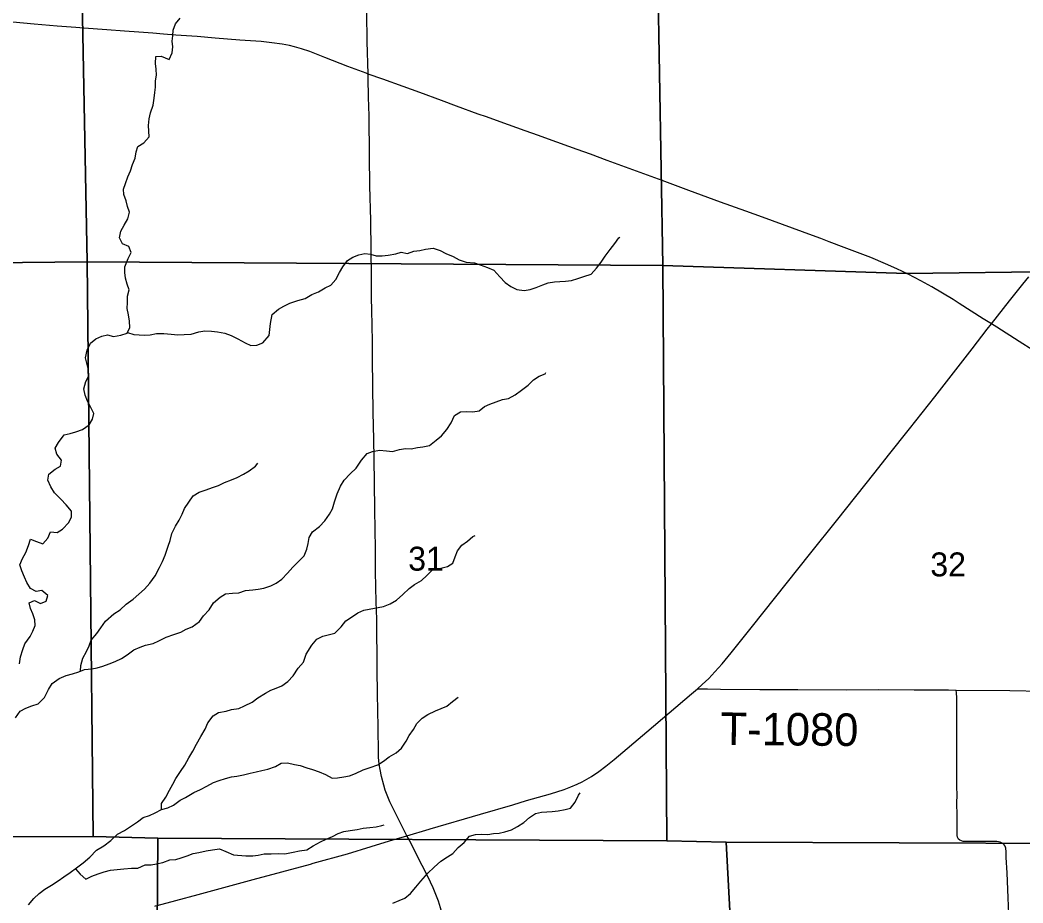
# Model space of a CAD drawing. Extents: x 0 to 34, y 0 to 22.
# Drawn here: x 11.363 to 13.115, y 13.199 to 14.742 of the extents above; entities that cross this region are included whole.
import ezdxf

# ---------------------------------------------------------------- set-up
doc = ezdxf.new("R2010")
doc.units = 0
for name, color, linetype in [('GM_X_Minor_River', 7, 'Continuous'), ('GM_X_Section', 7, 'Continuous'), ('GM_X_Section_Text', 7, 'Continuous'), ('GM_X_State_Route', 7, 'Continuous'), ('GM_X_Township_Road', 7, 'Continuous'), ('GM_X_Township_Road_Text', 7, 'Continuous'), ('GM_X_US_Route', 7, 'Continuous')]:
    doc.layers.add(name, color=color, linetype=linetype)

msp = doc.modelspace()

# ---------------------------------------------------------------- linework, layer by layer
at = {"layer": 'GM_X_Minor_River'}
for points in [[(11.4605, 14.0224), (11.4723, 14.0268), (11.4841, 14.0347), (11.4899, 14.0445), (11.4922, 14.0543), (11.4867, 14.065), (11.4811, 14.076), (11.477, 14.0867), (11.4748, 14.0977), (11.478, 14.1102), (11.4833, 14.1204), (11.483, 14.1307), (11.4805, 14.1402), (11.4779, 14.1516), (11.4803, 14.1652), (11.4861, 14.1773), (11.4956, 14.1848), (11.5063, 14.1896), (11.5161, 14.1918), (11.5267, 14.1891), (11.5392, 14.1912), (11.5502, 14.1949), (11.5552, 14.2051), (11.5546, 14.2161), (11.5528, 14.2267), (11.5506, 14.2378), (11.5511, 14.2488), (11.5508, 14.2594), (11.5539, 14.2704), (11.5502, 14.2806), (11.5473, 14.2909), (11.5462, 14.3008), (11.5463, 14.3107), (11.5521, 14.3254), (11.5575, 14.336), (11.5534, 14.3463), (11.5421, 14.3509), (11.5373, 14.3616), (11.5396, 14.373), (11.545, 14.3839), (11.5516, 14.3945), (11.5547, 14.4066), (11.551, 14.4161), (11.5484, 14.426), (11.5447, 14.437), (11.544, 14.4465), (11.5475, 14.4567), (11.5518, 14.4681), (11.5561, 14.4787), (11.5596, 14.4896), (11.5646, 14.501), (11.5662, 14.5116), (11.5689, 14.5214), (11.5796, 14.5274), (11.5887, 14.5379), (11.5881, 14.5482), (11.5878, 14.5576), (11.5886, 14.5694), (11.5914, 14.58), (11.596, 14.5932), (11.5976, 14.6057), (11.5985, 14.6156), (11.5997, 14.6251), (11.5998, 14.6357), (11.6014, 14.6459), (11.6011, 14.6562), (11.5997, 14.6664), (11.6002, 14.6782), (11.61, 14.6788), (11.6236, 14.6734), (11.629, 14.6847), (11.6302, 14.6953), (11.6292, 14.7052), (11.6304, 14.7147), (11.6308, 14.7242), (11.6351, 14.7355), (11.6431, 14.7453)], [(11.5509, 14.1962), (11.5623, 14.1925), (11.5805, 14.1912), (11.5907, 14.1922), (11.6017, 14.1944), (11.6142, 14.1943), (11.6275, 14.193), (11.6392, 14.1921), (11.6498, 14.1928), (11.6623, 14.1934), (11.6756, 14.1971), (11.6858, 14.1989), (11.6979, 14.1984), (11.7082, 14.1975), (11.721, 14.1947), (11.7323, 14.1908), (11.744, 14.185), (11.7565, 14.1781), (11.7666, 14.1731), (11.7769, 14.1737), (11.7875, 14.1778), (11.7982, 14.191), (11.7998, 14.2016), (11.8007, 14.2118), (11.8035, 14.2277), (11.8145, 14.2367), (11.824, 14.2423), (11.8347, 14.2471), (11.8487, 14.2523), (11.8613, 14.2556), (11.8731, 14.2627), (11.8848, 14.2671), (11.8963, 14.2742), (11.9061, 14.2791), (11.9149, 14.2889), (11.9215, 14.3009), (11.9269, 14.3107), (11.9353, 14.3217), (11.9448, 14.3276), (11.9551, 14.3321), (11.9657, 14.3339), (11.9755, 14.333), (11.9853, 14.3299), (11.9956, 14.3298), (12.0062, 14.3312), (12.0198, 14.3337), (12.0293, 14.3367), (12.0403, 14.3343), (12.0509, 14.338), (12.0615, 14.3394), (12.0718, 14.342), (12.0847, 14.3434), (12.0971, 14.3394), (12.1073, 14.3344), (12.1198, 14.329), (12.1303, 14.3232), (12.1428, 14.3189), (12.1571, 14.318), (12.167, 14.3145), (12.1798, 14.3098), (12.1911, 14.3048), (12.2016, 14.2933), (12.2106, 14.2837), (12.2208, 14.2764), (12.2313, 14.2713), (12.2438, 14.2697), (12.2544, 14.2711), (12.2651, 14.2748), (12.2765, 14.2796), (12.286, 14.2826), (12.2966, 14.2844), (12.3061, 14.2854), (12.3163, 14.2857), (12.3265, 14.2871), (12.3375, 14.2904), (12.3482, 14.2937), (12.3607, 14.2982), (12.3703, 14.3083), (12.3783, 14.3192), (12.3852, 14.3294), (12.394, 14.3411), (12.4021, 14.3516), (12.4093, 14.3618), (12.4109, 14.3629)], [(11.3552, 13.5229), (11.3636, 13.5346), (11.3735, 13.5398), (11.3838, 13.5435), (11.3952, 13.5472), (11.4059, 13.5581), (11.4132, 13.5724), (11.4193, 13.5826), (11.4319, 13.5916), (11.4437, 13.5968), (11.4547, 13.5997), (11.4661, 13.6034), (11.476, 13.6071), (11.4885, 13.6085), (11.4979, 13.6103), (11.5078, 13.6132), (11.5192, 13.6173), (11.5295, 13.6214), (11.5405, 13.6266), (11.5504, 13.6326), (11.5622, 13.6415), (11.5732, 13.646), (11.5827, 13.6497), (11.5956, 13.6526), (11.6059, 13.6571), (11.6188, 13.6634), (11.6317, 13.6682), (11.6439, 13.6726), (11.6534, 13.6775), (11.664, 13.6815), (11.6766, 13.6909), (11.6835, 13.7007), (11.6934, 13.7116), (11.7015, 13.7237), (11.7126, 13.7338), (11.7221, 13.7394), (11.7346, 13.7404), (11.7452, 13.7411), (11.757, 13.7455), (11.7698, 13.7465), (11.7793, 13.7476), (11.7892, 13.7494), (11.8013, 13.7534), (11.8108, 13.7583), (11.8207, 13.765), (11.8307, 13.7755), (11.8399, 13.7861), (11.8597, 13.8056), (11.864, 13.8177), (11.8663, 13.8275), (11.8683, 13.8378), (11.8741, 13.848), (11.8863, 13.8573), (11.8958, 13.8671), (11.9039, 13.8784), (11.9093, 13.8882), (11.9124, 13.9), (11.9171, 13.9139), (11.9232, 13.9275), (11.9297, 13.9381), (11.9401, 13.949), (11.9504, 13.9592), (11.96, 13.9731), (11.9695, 13.9844), (11.979, 13.9881), (11.9912, 13.9906), (12.0033, 13.9894), (12.0139, 13.9881), (12.026, 13.9918), (12.0366, 13.9936), (12.0465, 13.9927), (12.0575, 13.9949), (12.0669, 13.9963), (12.0787, 13.9989), (12.0901, 14.0079), (12.0997, 14.0158), (12.1089, 14.0267), (12.1161, 14.0384), (12.1223, 14.0508), (12.1326, 14.0572), (12.1432, 14.0582), (12.1542, 14.0577), (12.1652, 14.0591), (12.1747, 14.0666), (12.1842, 14.0711), (12.1948, 14.0752), (12.2062, 14.0788), (12.2165, 14.081), (12.2279, 14.0874), (12.2393, 14.0956), (12.2508, 14.1042), (12.2603, 14.1132), (12.2702, 14.1196), (12.2805, 14.124), (12.282, 14.1263)], [(11.3624, 13.6173), (11.3641, 13.6291), (11.3683, 13.6423), (11.3715, 13.6521), (11.381, 13.6646), (11.3857, 13.6744), (11.3895, 13.6842), (11.3892, 13.6941), (11.3859, 13.7044), (11.3814, 13.7139), (11.3792, 13.7234), (11.3888, 13.7275), (11.3989, 13.7224), (11.4092, 13.7265), (11.4119, 13.7364), (11.4014, 13.7452), (11.3912, 13.7434), (11.3814, 13.7488), (11.375, 13.7591), (11.3713, 13.7686), (11.3665, 13.7797), (11.3628, 13.79), (11.3678, 13.8013), (11.3732, 13.8119), (11.3778, 13.8236), (11.3813, 13.8349), (11.3923, 13.8306), (11.4032, 13.8267), (11.412, 13.8369), (11.4167, 13.8479), (11.428, 13.8466), (11.4375, 13.8526), (11.4486, 13.8639), (11.4532, 13.8737), (11.4533, 13.8839), (11.4439, 13.8947), (11.4346, 13.905), (11.4233, 13.9161), (11.4169, 13.9264), (11.4121, 13.9382), (11.4137, 13.9484), (11.4244, 13.9575), (11.4339, 13.9627), (11.4355, 13.9729), (11.4276, 13.9832), (11.4247, 13.9939), (11.4305, 14.0041), (11.4401, 14.0173), (11.4511, 14.0198), (11.4605, 14.0224)], [(11.4691, 13.6045), (11.4692, 13.6144), (11.4727, 13.6269), (11.4793, 13.6386), (11.4843, 13.6484), (11.4874, 13.6582), (11.4973, 13.6703), (11.5042, 13.6801), (11.5126, 13.6917), (11.5271, 13.7045), (11.5382, 13.7116), (11.5485, 13.7214), (11.5607, 13.73), (11.5706, 13.7386), (11.5809, 13.7476), (11.5901, 13.7578), (11.5993, 13.771), (11.607, 13.7853), (11.6124, 13.7959), (11.6166, 13.8072), (11.6221, 13.8227), (11.6256, 13.8329), (11.6287, 13.845), (11.6348, 13.8579), (11.6414, 13.8681), (11.6464, 13.8786), (11.6503, 13.8885), (11.6583, 13.8998), (11.6656, 13.9107), (11.6762, 13.9171), (11.6884, 13.9211), (11.6994, 13.9252), (11.71, 13.9289), (11.7207, 13.9337), (11.7325, 13.9385), (11.7423, 13.9426), (11.7538, 13.9486), (11.7637, 13.9541), (11.7747, 13.9628), (11.7789, 13.968)], [(11.6102, 13.3626), (11.6103, 13.3732), (11.618, 13.3841), (11.6241, 13.3966), (11.6299, 13.4071), (11.6357, 13.417), (11.6433, 13.429), (11.651, 13.4403), (11.6583, 13.4528), (11.6652, 13.4645), (11.6714, 13.4766), (11.6791, 13.4901), (11.6867, 13.503), (11.6914, 13.5139), (11.7006, 13.526), (11.7101, 13.532), (11.7234, 13.5345), (11.7329, 13.5374), (11.7457, 13.5392), (11.7553, 13.5437), (11.7686, 13.55), (11.7785, 13.5575), (11.7918, 13.5657), (11.8013, 13.5713), (11.8108, 13.5746), (11.8203, 13.5787), (11.8313, 13.5862), (11.8405, 13.596), (11.8493, 13.6095), (11.8585, 13.6201), (11.8632, 13.6337), (11.8728, 13.6495), (11.8816, 13.6604), (11.8922, 13.6657), (11.9017, 13.6678), (11.9131, 13.6704), (11.9242, 13.6817), (11.9326, 13.6922), (11.9425, 13.6986), (11.9535, 13.706), (11.9638, 13.7109), (11.9979, 13.7174), (12.0097, 13.7222), (12.0207, 13.7281), (12.0322, 13.7383), (12.0429, 13.7488), (12.0524, 13.7559), (12.0646, 13.7626), (12.0741, 13.7713), (12.0837, 13.7814), (12.0935, 13.7832), (12.1098, 13.7872), (12.1194, 13.7928), (12.1236, 13.8038), (12.1275, 13.8144), (12.1348, 13.8242), (12.1447, 13.8317), (12.1542, 13.8395), (12.1584, 13.8414)], [(11.3778, 13.196), (11.3874, 13.2073), (11.3969, 13.2159), (11.4064, 13.2234), (11.4182, 13.2305), (11.43, 13.238), (11.4399, 13.2447), (11.4506, 13.2522), (11.462, 13.2604), (11.4735, 13.2694), (11.4853, 13.2792), (11.4971, 13.2912), (11.5097, 13.299), (11.5219, 13.3084), (11.5337, 13.3197), (11.5459, 13.326), (11.5577, 13.3339), (11.5684, 13.341), (11.5783, 13.3488), (11.5893, 13.3521), (11.5996, 13.3566), (11.6102, 13.3626), (11.6216, 13.3655), (11.6315, 13.3699), (11.6429, 13.3789), (11.6524, 13.3838), (11.6669, 13.3924), (11.6783, 13.3976), (11.6893, 13.4035), (11.7015, 13.4099), (11.711, 13.4132), (11.722, 13.4169), (11.7326, 13.4198), (11.7421, 13.4209), (11.7535, 13.423), (11.7652, 13.4259), (11.7759, 13.4285), (11.7857, 13.4307), (11.796, 13.4332), (11.8093, 13.4377), (11.8195, 13.4436), (11.8305, 13.4439), (11.8426, 13.4411), (11.8524, 13.4395), (11.8641, 13.4352), (11.874, 13.4325), (11.8857, 13.4282), (11.8966, 13.4235), (11.9083, 13.4173), (11.9181, 13.4176), (11.9291, 13.4198), (11.9386, 13.4216), (11.9493, 13.4253), (11.9626, 13.432), (11.9751, 13.436), (11.988, 13.4405), (11.9983, 13.4468), (12.0082, 13.4547), (12.0204, 13.4618), (12.0299, 13.47), (12.0376, 13.4817), (12.043, 13.4919), (12.0503, 13.5025), (12.0564, 13.5127), (12.0656, 13.5224), (12.0758, 13.5284), (12.0892, 13.5347), (12.1089, 13.5429), (12.1188, 13.5511), (12.1284, 13.559)], [(12.0147, 13.1989), (12.0254, 13.2033), (12.0356, 13.2074), (12.0452, 13.2157), (12.0547, 13.2269), (12.0635, 13.2371), (12.0758, 13.251), (12.0865, 13.2619), (12.0983, 13.2721), (12.1097, 13.2799), (12.1192, 13.2855), (12.1284, 13.2964), (12.1391, 13.305), (12.1486, 13.316), (12.1589, 13.3189), (12.1691, 13.3192), (12.1805, 13.3191), (12.1903, 13.3205), (12.2002, 13.3211), (12.21, 13.3233), (12.2218, 13.327), (12.2321, 13.333), (12.2431, 13.3401), (12.253, 13.3483), (12.2637, 13.3554), (12.274, 13.358), (12.2929, 13.3593), (12.3035, 13.3604), (12.3156, 13.3625), (12.3251, 13.3651), (12.3332, 13.3753), (12.339, 13.3873), (12.3416, 13.3915)], [(11.4601, 13.259), (11.4684, 13.2493), (11.4785, 13.2409), (11.4888, 13.2461), (11.4998, 13.2502), (11.5105, 13.2539), (11.5211, 13.2568), (11.5446, 13.2589), (11.5578, 13.2602), (11.5692, 13.2601), (11.5821, 13.2657), (11.5923, 13.2656), (11.6018, 13.2678), (11.6125, 13.27), (11.625, 13.2748), (11.6352, 13.2754), (11.6447, 13.278), (11.6553, 13.2817), (11.6656, 13.2854), (11.6758, 13.2872), (11.6884, 13.2905), (11.6994, 13.2923), (11.7115, 13.2937), (11.7228, 13.289), (11.7364, 13.2832), (11.7576, 13.2814), (11.7697, 13.2817), (11.7795, 13.2827), (11.7898, 13.2849), (11.8019, 13.2848), (11.8155, 13.2854), (11.8258, 13.2853), (11.8402, 13.2882), (11.8512, 13.2904), (11.8641, 13.2922), (11.8755, 13.2989), (11.8884, 13.3063), (11.8983, 13.3108), (11.9093, 13.3153), (11.9188, 13.3205), (11.9287, 13.3242), (11.9401, 13.326), (11.9522, 13.3274), (11.9625, 13.3299), (11.9742, 13.3309), (11.9856, 13.3323), (11.9954, 13.3345), (11.9996, 13.336)]]:
    msp.add_lwpolyline(points, dxfattribs=at)
at = {"layer": 'GM_X_Section'}
for points in [[(11.4614, 15.3278), (11.4808, 14.3193), (10.464, 14.3093), (10.451, 15.3094)], [(12.4684, 15.3203), (12.486, 14.3129), (11.4808, 14.3193), (11.4614, 15.3278)], [(13.4573, 15.3188), (13.4623, 14.3061), (12.9117, 14.2993), (12.486, 14.3129), (12.4684, 15.3203)], [(11.4808, 14.3193), (11.4908, 13.3153), (10.6414, 13.315), (10.4845, 13.3164), (10.464, 14.3093)], [(11.4808, 14.3193), (12.486, 14.3129), (12.4929, 13.3075), (11.6037, 13.3127), (11.4908, 13.3153)], [(13.4623, 14.3061), (13.5034, 13.3022), (12.5967, 13.3052), (12.4929, 13.3075), (12.486, 14.3129), (12.9117, 14.2993)], [(11.4908, 13.3153), (11.6037, 13.3127), (11.5966, 12.2962), (11.5959, 12.2894), (10.6374, 12.2875), (10.6414, 13.315)], [(12.4929, 13.3075), (12.5967, 13.3052), (12.6535, 12.2476), (11.5966, 12.2962), (11.6037, 13.3127)], [(13.5034, 13.3022), (13.5746, 13.3006), (13.6043, 12.2869), (12.6535, 12.2476), (12.5967, 13.3052)]]:
    msp.add_lwpolyline(points, close=True, dxfattribs=at)
at = {"layer": 'GM_X_State_Route'}
for points in [[(11.9888, 13.4933), (11.9886, 13.5063), (11.9879, 13.5645), (11.9869, 13.6069), (11.9863, 13.6951), (11.9855, 13.7254), (11.9849, 13.7511), (11.9844, 13.7793), (11.984, 13.819), (11.9837, 13.8504), (11.9829, 13.8882), (11.982, 13.9757), (11.9814, 14.009), (11.9803, 14.0571), (11.9798, 14.1019), (11.979, 14.15), (11.9787, 14.1806), (11.9783, 14.2085), (11.9778, 14.2352), (11.9775, 14.2566), (11.977, 14.296), (11.9768, 14.3398), (11.976, 14.3921), (11.9745, 14.4522), (11.9735, 14.5042), (11.9729, 14.575), (11.9722, 14.6072), (11.9716, 14.6404), (11.9714, 14.6478), (11.9699, 14.7049), (11.969, 14.7549)], [(11.461, 14.7289), (11.4283, 14.7315), (11.3881, 14.7351), (11.3509, 14.7383)], [(13.0601, 14.2114), (13.0456, 14.2202), (13.0038, 14.247), (12.9933, 14.2536), (12.9558, 14.2758), (12.9368, 14.2864), (12.9147, 14.2979), (12.8951, 14.3074), (12.8752, 14.3163), (12.8494, 14.327), (12.803, 14.3449), (12.7767, 14.3545), (12.7623, 14.3602), (12.7478, 14.3657), (12.6601, 14.3976), (12.6309, 14.4082), (12.5871, 14.424), (12.5316, 14.4442), (12.485, 14.4617), (12.4529, 14.4733), (12.3887, 14.4968), (12.3596, 14.5076), (12.3362, 14.516), (12.2866, 14.5341), (12.269, 14.5403), (12.2456, 14.5487), (12.2018, 14.5645), (12.1783, 14.5727), (12.1637, 14.5779), (12.1258, 14.5919), (12.0996, 14.6016), (12.0616, 14.6153), (12.0323, 14.6257), (11.9973, 14.6386), (11.9714, 14.6478), (11.968, 14.649), (11.9361, 14.661), (11.8956, 14.6769), (11.8695, 14.6869), (11.8548, 14.692), (11.8428, 14.6954), (11.8337, 14.6975), (11.8214, 14.6997), (11.8029, 14.7023), (11.7843, 14.7044), (11.7472, 14.7072), (11.7039, 14.7106), (11.6729, 14.7131), (11.6357, 14.7159), (11.6141, 14.7176), (11.5955, 14.7189), (11.5707, 14.7208), (11.546, 14.7227), (11.515, 14.725), (11.4748, 14.7278), (11.461, 14.7289)], [(13.1323, 14.1654), (13.1088, 14.1805), (13.0695, 14.2057), (13.0601, 14.2114)], [(12.0392, 13.3167), (12.0162, 13.3619), (12.0094, 13.3759), (12.0045, 13.3874), (12.0013, 13.3961), (11.9985, 13.4051), (11.9946, 13.4202), (11.9921, 13.4324), (11.9907, 13.4417), (11.9896, 13.4541), (11.9892, 13.4744), (11.9888, 13.4933)], [(12.0441, 13.3076), (12.0434, 13.309), (12.0419, 13.3117), (12.0392, 13.3167)], [(12.108, 13.1024), (12.1061, 13.1327), (12.104, 13.1574), (12.1023, 13.1697), (12.1, 13.1818), (12.0977, 13.1908), (12.0941, 13.2026), (12.0898, 13.2142), (12.0849, 13.2256), (12.0755, 13.2452), (12.0561, 13.2841), (12.0441, 13.3076)]]:
    msp.add_lwpolyline(points, dxfattribs=at)
at = {"layer": 'GM_X_Township_Road'}
for points in [[(12.5465, 13.5736), (12.5641, 13.5733), (12.5871, 13.5729), (12.6555, 13.5725), (12.7222, 13.5721), (12.8071, 13.5717), (12.8628, 13.5721), (12.9251, 13.5717), (12.9853, 13.5715), (12.9987, 13.5712)], [(13.0165, 13.3064), (13.0155, 13.3064), (13.0124, 13.3066), (13.0106, 13.3068), (13.0077, 13.3075), (13.005, 13.3087), (13.0025, 13.3109), (13.0009, 13.3141), (13.0004, 13.317), (13, 13.3204), (13, 13.3296), (13, 13.3544), (12.9999, 13.3716), (13, 13.3898), (12.9998, 13.4005), (12.9998, 13.4152), (12.9996, 13.4317), (12.9999, 13.4627), (12.9999, 13.5184), (12.9998, 13.5463), (12.9994, 13.5577), (12.9991, 13.5664), (12.9987, 13.5712)], [(12.9987, 13.5712), (13.092, 13.5705), (13.1489, 13.5696)], [(13.0696, 13.3064), (13.0688, 13.3065), (13.0617, 13.3065), (13.0165, 13.3064)], [(13.1046, 12.8843), (13.1034, 12.9074), (13.1025, 12.926), (13.1012, 12.9508), (13.1003, 12.9694), (13.0984, 13.0128), (13.0962, 13.0625), (13.0931, 13.1276), (13.092, 13.1484), (13.0905, 13.1803), (13.0891, 13.2084), (13.0874, 13.2518), (13.0861, 13.2786), (13.0858, 13.2887), (13.0851, 13.2951), (13.084, 13.2984), (13.0824, 13.3009), (13.0802, 13.3029), (13.0779, 13.3042), (13.0751, 13.3054), (13.0722, 13.306), (13.0696, 13.3064)]]:
    msp.add_lwpolyline(points, dxfattribs=at)
at = {"layer": 'GM_X_US_Route'}
msp.add_line((12.0089, 13.3076), (12.0392, 13.3167), dxfattribs=at)
for points in [[(13.0601, 14.2114), (13.0914, 14.2512), (13.1148, 14.2805), (13.1257, 14.2936)], [(12.0799, 13.3287), (12.1674, 13.3544), (12.2242, 13.3708), (12.248, 13.3781), (12.2897, 13.3902), (12.3135, 13.3977), (12.3252, 13.4019), (12.3367, 13.4067), (12.3452, 13.4108), (12.3534, 13.4153), (12.3614, 13.4202), (12.3743, 13.429), (12.3868, 13.4382), (12.4013, 13.4499), (12.4581, 13.4983), (12.5363, 13.5646), (12.5465, 13.5736), (12.5551, 13.581), (12.5664, 13.5917), (12.5771, 13.603), (12.5895, 13.617), (12.6054, 13.6362), (12.6404, 13.6798), (12.7449, 13.8112), (12.7894, 13.8671), (12.8573, 13.9521), (12.8803, 13.9815), (12.9171, 14.0277), (12.9613, 14.0839), (13.0262, 14.1673), (13.0526, 14.2018), (13.0601, 14.2114)], [(12.0392, 13.3167), (12.078, 13.3282), (12.0799, 13.3287)], [(11.8706, 13.2672), (11.8754, 13.2685), (11.9352, 13.2853), (11.9767, 13.2981), (12.0089, 13.3076)], [(11.5988, 13.1939), (11.5998, 13.1941), (11.6026, 13.1948), (11.6356, 13.2034), (11.6746, 13.2139), (11.7704, 13.2403), (11.8706, 13.2672)]]:
    msp.add_lwpolyline(points, dxfattribs=at)

# ---------------------------------------------------------------- texts
at = {"layer": 'GM_X_Section_Text'}
for s, p in [('31', (12.0413, 13.7799)), ('32', (12.9534, 13.7699))]:
    msp.add_text(s, height=0.04186, rotation=0, dxfattribs=at).set_placement(p)
at = {"layer": 'GM_X_Township_Road_Text'}
msp.add_text('T-1080', height=0.05682, rotation=359.5312, dxfattribs=at).set_placement((12.5868, 13.4754))

doc.saveas('drawing.dxf')
